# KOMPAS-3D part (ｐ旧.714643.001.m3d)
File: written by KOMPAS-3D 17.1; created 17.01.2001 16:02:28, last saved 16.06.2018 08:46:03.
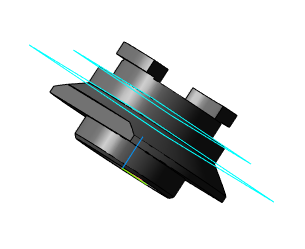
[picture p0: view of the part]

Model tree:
1. Фронтальная плоскость
2. Горизонтальная плоскость
3. Профильная плоскость
4. Начало координат
5. Эскиз:3
6. Приклеить элемент выдавливания:1
     Расстояние 1 = 7
7. Эскиз:4
8. Приклеить элемент выдавливания:2
     Расстояние 1 = 2
9. Смещенная плоскость:1
     Расстояние = 6
10. Эскиз:5
11. Приклеить элемент выдавливания:3
     Расстояние 1 = 15
12. Эскиз:6
13. Эскиз:7
14. Приклеить элемент по сечениям:1
     Толщина стенки 1 = 1; Толщина стенки 2 = 1
15. Эскиз:8
16. Вырезать элемент выдавливания:2
     Расстояние 1 = 11.5
17. Смещенная плоскость:2
     Расстояние = 9.5
18. Эскиз:9
19. Вырезать элемент выдавливания:3
     Расстояние 2 = 5.5
20. Фаска:1
     Угол = 45; Длина 1 = 1; Длина 2 = 1
21. Эскиз:10
22. Вырезать элемент выдавливания:4
     Расстояние 1 = 13.5
23. Эскиз:11
24. Вырезать элемент выдавливания:5
     Расстояние 2 = 5.5; Расстояние 1 = 53.5
25. Эскиз:12
26. Вырезать элемент выдавливания:6
     Расстояние 2 = 5.5; Расстояние 1 = 53.5
27. Сечение плоскостью:1
28. Сечение плоскостью:2  (labels: Сталь 40Х13 ГОСТ 5632-2014)

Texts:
  ВРЛМ.714643.001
